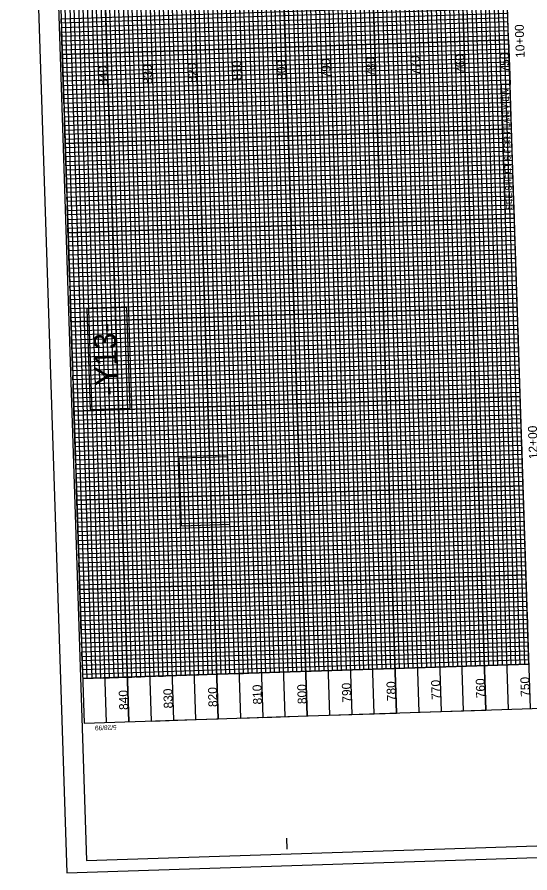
# Model space of a CAD drawing. Extents: x 1627314 to 1628469, y 762309 to 764245.
# Drawn here: x 1627314 to 1627888, y 762309 to 763268 of the extents above; entities that cross this region are included whole.
import ezdxf

# ---------------------------------------------------------------- set-up
doc = ezdxf.new("R2010")
doc.units = 0
for name, color, linetype in [('Exist Vertical Profile Horizontal Axis Label Major', 7, 'Continuous'), ('Exist Vertical Profile Vertical Axis Label', 7, 'Continuous'), ('Prop DSN Text', 7, 'Continuous'), ('Prop Grid Mask', 7, 'Continuous'), ('Sheet Data Field CELL', 7, 'Continuous'), ('Sheet DOT Grid CELL', 7, 'Continuous'), ('Sheet Layout Profile Border Port 1', 7, 'Continuous'), ('Sheet Plot Border Inside CELL', 7, 'Continuous'), ('Sheet Plot Border Outside CELL', 7, 'Continuous'), ('Sheet Profile CELL', 7, 'Continuous'), ('Sheet Profile Grid Major CELL', 7, 'Continuous'), ('Sheet Profile Grid Middle CELL', 7, 'Continuous'), ('Sheet Profile Grid Minor CELL', 7, 'Continuous')]:
    doc.layers.add(name, color=color, linetype=linetype)

msp = doc.modelspace()

# ---------------------------------------------------------------- linework, layer by layer
at = {"layer": 'Prop Grid Mask'}
for points in [[(1627366.44, 763176.67), (1627364.8, 763226.64), (1627864.53, 763242.99), (1627866.17, 763193.01)], [(1627856.17, 763192.69), (1627860.92, 763047.76), (1627870.91, 763048.09), (1627866.17, 763193.01)], [(1627440.71, 762829.99), (1627437.01, 762943.01), (1627392.29, 762941.55), (1627395.99, 762828.53)], [(1627498.23, 762697.91), (1627495.73, 762774.33), (1627549.41, 762776.08), (1627551.91, 762699.67)]]:
    msp.add_lwpolyline(points, close=True, dxfattribs=at)
at = {"layer": 'Sheet DOT Grid CELL'}
for p, q in [((1627640.12, 763986.05), (1627689.16, 762486.85)), ((1627690.1, 763987.68), (1627739.13, 762488.48)), ((1627740.07, 763989.32), (1627789.11, 762490.12)), ((1627790.04, 763990.95), (1627839.08, 762491.75)), ((1627590.15, 763984.41), (1627639.19, 762485.21)), ((1627396.8, 763777.93), (1627439.29, 762478.68)), ((1627446.77, 763779.57), (1627489.27, 762480.31)), ((1627496.74, 763781.25), (1627539.24, 762481.95)), ((1627546.72, 763782.83), (1627589.21, 762483.58)), ((1627864.53, 763242.99), (1627364.8, 763226.64)), ((1627866.17, 763193.01), (1627366.44, 763176.67)), ((1627867.8, 763143.04), (1627368.07, 763126.69)), ((1627869.44, 763093.07), (1627369.71, 763076.72)), ((1627871.07, 763043.09), (1627371.34, 763026.75)), ((1627872.71, 762993.12), (1627372.98, 762976.77)), ((1627874.34, 762943.15), (1627374.61, 762926.8)), ((1627875.98, 762893.17), (1627376.24, 762876.83)), ((1627877.61, 762843.2), (1627377.88, 762826.85)), ((1627879.25, 762793.23), (1627379.51, 762776.88)), ((1627880.88, 762743.25), (1627381.15, 762726.91)), ((1627882.52, 762693.28), (1627382.78, 762676.93)), ((1627884.15, 762643.31), (1627384.42, 762626.96)), ((1627885.78, 762593.33), (1627386.05, 762576.99)), ((1627887.42, 762543.36), (1627387.69, 762527.01))]:
    msp.add_line(p, q, dxfattribs=at)
at = {"layer": 'Sheet Layout Profile Border Port 1'}
msp.add_lwpolyline([(1627548.65, 762532.28), (1627887.42, 762543.36), (1627841.65, 763942.61), (1627566.8, 763933.62)], dxfattribs=at)
at = {"layer": 'Sheet Plot Border Inside CELL'}
msp.add_lwpolyline([(1628446.34, 762357.53), (1628391.86, 764023.14), (1627337.33, 763988.65), (1627391.81, 762323.04)], close=True, dxfattribs=at)
at = {"layer": 'Sheet Plot Border Outside CELL'}
msp.add_lwpolyline([(1628469.21, 762345.27), (1628413.63, 764044.37), (1627314.22, 764008.4), (1627369.79, 762309.31)], close=True, dxfattribs=at)
at = {"layer": 'Sheet Profile CELL'}
for p, q in [((1627889.05, 762493.39), (1627840.02, 763992.59)), ((1627616.56, 762335.89), (1627616.15, 762348.39))]:
    msp.add_line(p, q, dxfattribs=at)
msp.add_lwpolyline([(1627340.28, 763976.24), (1627389.32, 762477.04), (1628438.76, 762511.37), (1628389.72, 764010.57)], close=True, dxfattribs=at)
at = {"layer": 'Sheet Profile Grid Major CELL'}
for points in [[(1627640.12, 763986.05), (1627689.16, 762486.85), (1627739.13, 762488.48), (1627690.1, 763987.68)], [(1627740.07, 763989.32), (1627789.11, 762490.12), (1627789.11, 762490.12), (1627839.08, 762491.75), (1627790.04, 763990.95)], [(1627546.71, 763782.88), (1627589.21, 762483.58), (1627639.19, 762485.21), (1627590.15, 763984.41)], [(1627439.29, 762478.68), (1627396.79, 763777.98)], [(1627446.77, 763779.62), (1627489.27, 762480.31), (1627539.24, 762481.95), (1627496.74, 763781.25)], [(1627387.69, 762527.01), (1627887.42, 762543.36), (1627885.78, 762593.33), (1627386.05, 762576.99), (1627384.42, 762626.96), (1627884.15, 762643.31), (1627882.52, 762693.28), (1627382.78, 762676.93), (1627381.15, 762726.91), (1627880.88, 762743.25), (1627879.25, 762793.23), (1627379.51, 762776.88), (1627377.88, 762826.85), (1627877.61, 762843.2), (1627875.98, 762893.17), (1627376.24, 762876.83), (1627374.61, 762926.8), (1627874.34, 762943.15), (1627872.71, 762993.12), (1627372.98, 762976.77), (1627371.34, 763026.75), (1627871.07, 763043.09), (1627869.44, 763093.07), (1627369.71, 763076.72), (1627368.07, 763126.69), (1627867.8, 763143.04), (1627866.17, 763193.01), (1627366.44, 763176.67), (1627364.8, 763226.64), (1627864.53, 763242.99), (1627862.9, 763292.96)]]:
    msp.add_lwpolyline(points, dxfattribs=at)
at = {"layer": 'Sheet Profile Grid Middle CELL'}
msp.add_line((1627414.31, 762477.86), (1627371.81, 763777.11), dxfattribs=at)
for points in [[(1627615.14, 763985.23), (1627664.17, 762486.03), (1627714.15, 762487.67), (1627665.11, 763986.86)], [(1627715.08, 763988.5), (1627764.12, 762489.3), (1627814.09, 762490.94), (1627765.06, 763990.13)], [(1627815.03, 763991.77), (1627864.07, 762492.57)], [(1627521.73, 763782.02), (1627564.23, 762482.76), (1627614.2, 762484.4), (1627570.88, 763808.69)], [(1627421.78, 763778.8), (1627464.28, 762479.49), (1627514.25, 762481.13), (1627471.75, 763780.43)], [(1627386.87, 762552), (1627886.6, 762568.35), (1627884.97, 762618.32), (1627385.23, 762601.97), (1627383.6, 762651.95), (1627883.33, 762668.29), (1627881.7, 762718.27), (1627381.97, 762701.92), (1627380.33, 762751.89), (1627880.06, 762768.24), (1627878.43, 762818.21), (1627378.7, 762801.87), (1627377.06, 762851.84), (1627876.79, 762868.19), (1627875.16, 762918.16), (1627375.43, 762901.81), (1627373.79, 762951.79), (1627873.53, 762968.13), (1627871.89, 763018.11), (1627372.16, 763001.76), (1627370.52, 763051.73), (1627870.26, 763068.08), (1627868.62, 763118.05), (1627868.62, 763118.05), (1627368.89, 763101.71), (1627367.25, 763151.68), (1627866.99, 763168.03), (1627865.35, 763218), (1627365.62, 763201.65), (1627363.98, 763251.63), (1627863.72, 763267.97), (1627862.08, 763317.95)]]:
    msp.add_lwpolyline(points, dxfattribs=at)
at = {"layer": 'Sheet Profile Grid Minor CELL'}
for p, q in [((1627702.52, 762537.31), (1627656.75, 763936.56)), ((1627661.75, 763936.73), (1627707.52, 762537.48)), ((1627717.51, 762537.8), (1627671.74, 763937.05)), ((1627676.74, 763937.22), (1627722.51, 762537.97)), ((1627727.51, 762538.13), (1627681.74, 763937.38)), ((1627686.73, 763937.55), (1627732.5, 762538.29)), ((1627742.5, 762538.62), (1627696.73, 763937.87)), ((1627701.73, 763938.04), (1627747.49, 762538.78)), ((1627752.49, 762538.95), (1627706.72, 763938.2)), ((1627711.72, 763938.36), (1627757.49, 762539.11)), ((1627767.48, 762539.44), (1627721.71, 763938.69)), ((1627726.71, 763938.85), (1627772.48, 762539.6)), ((1627731.71, 763939.02), (1627777.48, 762539.76)), ((1627736.71, 763939.18), (1627782.48, 762539.93)), ((1627792.47, 762540.25), (1627746.7, 763939.51)), ((1627751.7, 763939.67), (1627797.47, 762540.42)), ((1627802.47, 762540.58), (1627756.7, 763939.83)), ((1627761.69, 763940), (1627807.46, 762540.75)), ((1627817.46, 762541.07), (1627771.69, 763940.32)), ((1627776.69, 763940.49), (1627822.45, 762541.24)), ((1627827.45, 762541.4), (1627781.68, 763940.65)), ((1627786.68, 763940.81), (1627832.45, 762541.56)), ((1627842.44, 762541.89), (1627796.67, 763941.14)), ((1627801.67, 763941.3), (1627847.44, 762542.05)), ((1627852.44, 762542.22), (1627806.67, 763941.47)), ((1627811.67, 763941.63), (1627857.44, 762542.38)), ((1627867.43, 762542.71), (1627821.66, 763941.96)), ((1627826.66, 763942.12), (1627872.43, 762542.87)), ((1627877.42, 762543.03), (1627831.66, 763942.29)), ((1627576.79, 763933.95), (1627622.56, 762534.7)), ((1627627.56, 762534.86), (1627581.79, 763934.11)), ((1627586.79, 763934.28), (1627632.56, 762535.02)), ((1627642.55, 762535.35), (1627596.78, 763934.6)), ((1627601.78, 763934.77), (1627647.55, 762535.51)), ((1627652.55, 762535.68), (1627606.78, 763934.93)), ((1627611.77, 763935.09), (1627657.54, 762535.84)), ((1627667.54, 762536.17), (1627621.77, 763935.42)), ((1627626.77, 763935.58), (1627672.53, 762536.33)), ((1627677.53, 762536.5), (1627631.76, 763935.75)), ((1627636.76, 763935.91), (1627682.53, 762536.66)), ((1627692.52, 762536.99), (1627646.75, 763936.24)), ((1627651.75, 763936.4), (1627697.52, 762537.15)), ((1627556.71, 763783.16), (1627597.57, 762533.88)), ((1627602.57, 762534.04), (1627561.71, 763783.33)), ((1627392.68, 762527.18), (1627351.82, 763776.51)), ((1627356.82, 763776.67), (1627398.03, 762527.35)), ((1627402.68, 762527.5), (1627361.81, 763776.84)), ((1627481.75, 763780.71), (1627522.61, 762531.43)), ((1627486.75, 763780.92), (1627527.61, 762531.59)), ((1627491.74, 763781.09), (1627532.61, 762531.75)), ((1627542.6, 762532.08), (1627501.74, 763781.41)), ((1627506.74, 763781.58), (1627547.6, 762532.25)), ((1627552.6, 762532.41), (1627511.73, 763781.69)), ((1627531.72, 763782.34), (1627572.59, 762533.06)), ((1627577.59, 762533.23), (1627536.72, 763782.51)), ((1627397.68, 762527.34), (1627397.68, 762527.34))]:
    msp.add_line(p, q, dxfattribs=at)
for points in [[(1627836.65, 763942.45), (1627882.42, 762543.2)], [(1627566.71, 763783.49), (1627607.57, 762534.21), (1627617.56, 762534.53), (1627571.79, 763933.79)], [(1627366.81, 763777), (1627407.68, 762527.67), (1627417.67, 762528), (1627376.81, 763777.33)], [(1627381.8, 763777.44), (1627422.67, 762528.16), (1627427.67, 762528.32), (1627386.8, 763777.65)], [(1627391.8, 763777.82), (1627432.66, 762528.49), (1627442.66, 762528.81), (1627401.79, 763778.14)], [(1627406.79, 763778.31), (1627447.65, 762528.98), (1627452.65, 762529.14), (1627411.79, 763778.47)], [(1627416.78, 763778.63), (1627457.65, 762529.3), (1627467.64, 762529.63), (1627426.78, 763778.96)], [(1627431.78, 763779.13), (1627472.64, 762529.79), (1627477.64, 762529.96), (1627436.77, 763779.29)], [(1627441.77, 763779.45), (1627482.64, 762530.12), (1627492.63, 762530.45), (1627451.77, 763779.78)], [(1627456.86, 763779.95), (1627497.72, 762530.71), (1627502.62, 762530.87), (1627461.76, 763780.11)], [(1627466.76, 763780.27), (1627507.62, 762530.94), (1627517.62, 762531.26), (1627476.75, 763780.6)], [(1627516.73, 763781.85), (1627557.6, 762532.57), (1627567.59, 762532.9), (1627526.73, 763782.18)], [(1627541.72, 763782.67), (1627582.58, 762533.39), (1627592.58, 762533.72), (1627551.71, 763783)], [(1627863.39, 763277.97), (1627363.66, 763261.62), (1627363.49, 763266.62), (1627863.23, 763282.97)], [(1627370.36, 763056.73), (1627870.09, 763073.08), (1627869.93, 763078.07), (1627370.2, 763061.73), (1627370.03, 763066.73), (1627869.77, 763083.07), (1627869.6, 763088.07), (1627369.87, 763071.72), (1627369.54, 763081.72), (1627869.28, 763098.06), (1627869.11, 763103.06), (1627369.38, 763086.72), (1627369.22, 763091.71), (1627868.95, 763108.06), (1627868.78, 763113.06), (1627369.05, 763096.71), (1627368.73, 763106.7), (1627868.46, 763123.05), (1627868.29, 763128.05), (1627368.56, 763111.7), (1627368.4, 763116.7), (1627868.13, 763133.05), (1627867.97, 763138.04), (1627368.23, 763121.7), (1627367.91, 763131.69), (1627867.64, 763148.04), (1627867.48, 763153.03), (1627367.74, 763136.69), (1627367.58, 763141.69), (1627867.31, 763158.03), (1627867.15, 763163.03), (1627367.42, 763146.68), (1627367.09, 763156.68), (1627866.82, 763173.02), (1627866.66, 763178.02), (1627366.93, 763161.68), (1627366.76, 763166.67), (1627866.5, 763183.02), (1627866.33, 763188.02), (1627366.6, 763171.67), (1627366.27, 763181.66), (1627866.01, 763198.01), (1627866.01, 763198.01), (1627865.84, 763203.01), (1627366.11, 763186.66), (1627365.95, 763191.66), (1627865.68, 763208.01), (1627865.52, 763213), (1627365.78, 763196.66), (1627365.46, 763206.65), (1627865.19, 763223), (1627865.03, 763227.99), (1627365.29, 763211.65), (1627365.13, 763216.65), (1627864.86, 763232.99), (1627864.7, 763237.99), (1627364.97, 763221.64), (1627364.64, 763231.64), (1627864.37, 763247.98), (1627864.21, 763252.98), (1627364.48, 763236.63), (1627364.31, 763241.63), (1627864.04, 763257.98), (1627863.88, 763262.98), (1627364.15, 763246.63), (1627363.82, 763256.62), (1627863.55, 763272.97)], [(1627880.39, 762758.25), (1627880.23, 762763.24), (1627380.49, 762746.9), (1627380.17, 762756.89), (1627879.9, 762773.24), (1627879.74, 762778.24), (1627380, 762761.89), (1627379.84, 762766.89), (1627879.57, 762783.23), (1627879.41, 762788.23), (1627379.68, 762771.88), (1627379.35, 762781.88), (1627879.08, 762798.22), (1627878.92, 762803.22), (1627379.19, 762786.88), (1627379.02, 762791.87), (1627878.76, 762808.22), (1627878.59, 762813.22), (1627378.86, 762796.87), (1627378.53, 762806.86), (1627878.27, 762823.21), (1627878.1, 762828.21), (1627378.37, 762811.86), (1627378.21, 762816.86), (1627877.94, 762833.21), (1627877.78, 762838.2), (1627378.04, 762821.86), (1627377.72, 762831.85), (1627877.45, 762848.2), (1627877.28, 762853.19), (1627377.55, 762836.85), (1627377.39, 762841.85), (1627877.12, 762858.19), (1627876.96, 762863.19), (1627377.23, 762846.84), (1627376.9, 762856.84), (1627876.63, 762873.18), (1627876.47, 762878.18), (1627376.73, 762861.84), (1627376.57, 762866.83), (1627876.3, 762883.18), (1627876.14, 762888.18), (1627376.41, 762871.83), (1627376.08, 762881.82), (1627875.81, 762898.17), (1627875.65, 762903.17), (1627375.92, 762886.82), (1627375.75, 762891.82), (1627875.49, 762908.17), (1627875.32, 762913.16), (1627375.59, 762896.82), (1627375.26, 762906.81), (1627875, 762923.16), (1627874.83, 762928.15), (1627375.1, 762911.81), (1627374.94, 762916.81), (1627874.67, 762933.15), (1627874.51, 762938.15), (1627374.77, 762921.8), (1627374.45, 762931.8), (1627874.18, 762948.14), (1627874.02, 762953.14), (1627374.28, 762936.8), (1627374.12, 762941.79), (1627873.85, 762958.14), (1627873.69, 762963.14), (1627373.96, 762946.79), (1627373.63, 762956.78), (1627873.36, 762973.13), (1627873.2, 762978.13), (1627373.47, 762961.78), (1627373.3, 762966.78), (1627873.03, 762983.13), (1627872.87, 762988.12), (1627373.14, 762971.78), (1627372.81, 762981.77), (1627872.54, 762998.12), (1627872.38, 763003.11), (1627372.65, 762986.77), (1627372.48, 762991.77), (1627872.22, 763008.11), (1627872.05, 763013.11), (1627372.32, 762996.76), (1627371.99, 763006.76), (1627871.73, 763023.1), (1627871.56, 763028.1), (1627371.83, 763011.76), (1627371.67, 763016.75), (1627871.4, 763033.1), (1627871.24, 763038.1), (1627371.5, 763021.75), (1627371.18, 763031.74), (1627870.91, 763048.09), (1627870.75, 763053.09), (1627371.01, 763036.74), (1627370.85, 763041.74), (1627870.58, 763058.09), (1627870.42, 763063.08), (1627370.69, 763046.74), (1627370.36, 763056.73)], [(1627387.52, 762532.01), (1627887.26, 762548.36), (1627887.09, 762553.36), (1627387.36, 762537.01), (1627387.2, 762542.01), (1627886.93, 762558.35), (1627886.77, 762563.35), (1627387.03, 762547), (1627386.71, 762557), (1627886.44, 762573.34), (1627886.28, 762578.34), (1627386.54, 762562), (1627386.38, 762566.99), (1627886.11, 762583.34), (1627885.95, 762588.34), (1627885.62, 762598.33), (1627885.46, 762603.33), (1627385.73, 762586.98), (1627385.56, 762591.98), (1627885.29, 762608.33), (1627885.13, 762613.32), (1627385.4, 762596.98), (1627385.07, 762606.97), (1627884.8, 762623.32), (1627884.64, 762628.32), (1627384.91, 762611.97), (1627384.74, 762616.97), (1627884.48, 762633.31), (1627884.31, 762638.31), (1627384.58, 762621.96), (1627384.25, 762631.96), (1627883.99, 762648.3), (1627883.82, 762653.3), (1627384.09, 762636.96), (1627383.93, 762641.95), (1627883.66, 762658.3), (1627883.5, 762663.3), (1627383.76, 762646.95), (1627383.44, 762656.95), (1627883.17, 762673.29), (1627883.01, 762678.29), (1627383.27, 762661.94), (1627383.11, 762666.94), (1627882.84, 762683.29), (1627882.68, 762688.28), (1627382.95, 762671.94), (1627382.62, 762681.93), (1627882.35, 762698.28), (1627882.19, 762703.28), (1627382.46, 762686.93), (1627382.29, 762691.93), (1627882.03, 762708.27), (1627881.86, 762713.27), (1627382.13, 762696.92), (1627381.8, 762706.92), (1627881.53, 762723.26), (1627881.37, 762728.26), (1627381.64, 762711.92), (1627381.48, 762716.91), (1627881.21, 762733.26), (1627881.04, 762738.26), (1627381.31, 762721.91), (1627380.98, 762731.9), (1627880.72, 762748.25), (1627880.55, 762753.25), (1627380.82, 762736.9), (1627380.66, 762741.9), (1627880.39, 762758.25)], [(1627885.95, 762588.34), (1627386.22, 762571.99), (1627385.89, 762581.99), (1627885.62, 762598.33)]]:
    msp.add_lwpolyline(points, dxfattribs=at)

# ---------------------------------------------------------------- texts
at = {"layer": 'Exist Vertical Profile Horizontal Axis Label Major'}
for s, p in [('10+00', (1627882.7, 763222.88)), ('12+00', (1627897.41, 762773.12))]:
    msp.add_text(s, height=10, rotation=91.87347, dxfattribs=at).set_placement(p)
at = {"layer": 'Exist Vertical Profile Vertical Axis Label'}
for s, p in [('750', (1627865.48, 763206.43)), ('810', (1627565.6, 763197.82)), ('800', (1627615.61, 763198.26)), ('790', (1627665.59, 763199.89)), ('780', (1627715.56, 763201.53)), ('770', (1627765.53, 763203.16)), ('760', (1627815.51, 763204.8)), ('840', (1627415.72, 763191.72)), ('830', (1627465.69, 763193.35)), ('820', (1627515.67, 763194.99)), ('760', (1627838.39, 762505.17)), ('750', (1627888.37, 762506.8)), ('810', (1627588.49, 762498.19)), ('800', (1627638.5, 762498.63)), ('790', (1627688.47, 762500.27)), ('780', (1627738.45, 762501.9)), ('770', (1627788.42, 762503.53)), ('840', (1627438.61, 762492.09)), ('830', (1627488.58, 762493.73)), ('820', (1627538.55, 762495.36))]:
    msp.add_text(s, height=10, rotation=91.87347, dxfattribs=at).set_placement(p)
at = {"layer": 'Prop DSN Text'}
msp.add_text('SEE SHEET 6 FOR PLAN VIEW', height=7, rotation=91.87347, dxfattribs=at).set_placement((1627868.81, 763052.61))
at = {"layer": 'Sheet Data Field CELL'}
msp.add_text('-Y13-', height=25, rotation=91.87347, dxfattribs=at).set_placement((1627427.18, 762844.38))
at = {"layer": 'Sheet Profile CELL'}
msp.add_text('5/28/99', height=5.25, rotation=181.87347, dxfattribs=at).set_placement((1627425.5, 762474.99))

doc.saveas('drawing.dxf')
